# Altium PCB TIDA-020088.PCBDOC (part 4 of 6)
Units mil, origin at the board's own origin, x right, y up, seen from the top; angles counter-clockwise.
Board outline 7520.69 x 5119.11 mil, 6 copper layers (TOP, GND02, SIG03, SIG04, GND05, BOTTOM), stack 87.024 mil thick; 539 components, 269 nets, 1479 pads, 2085 vias.
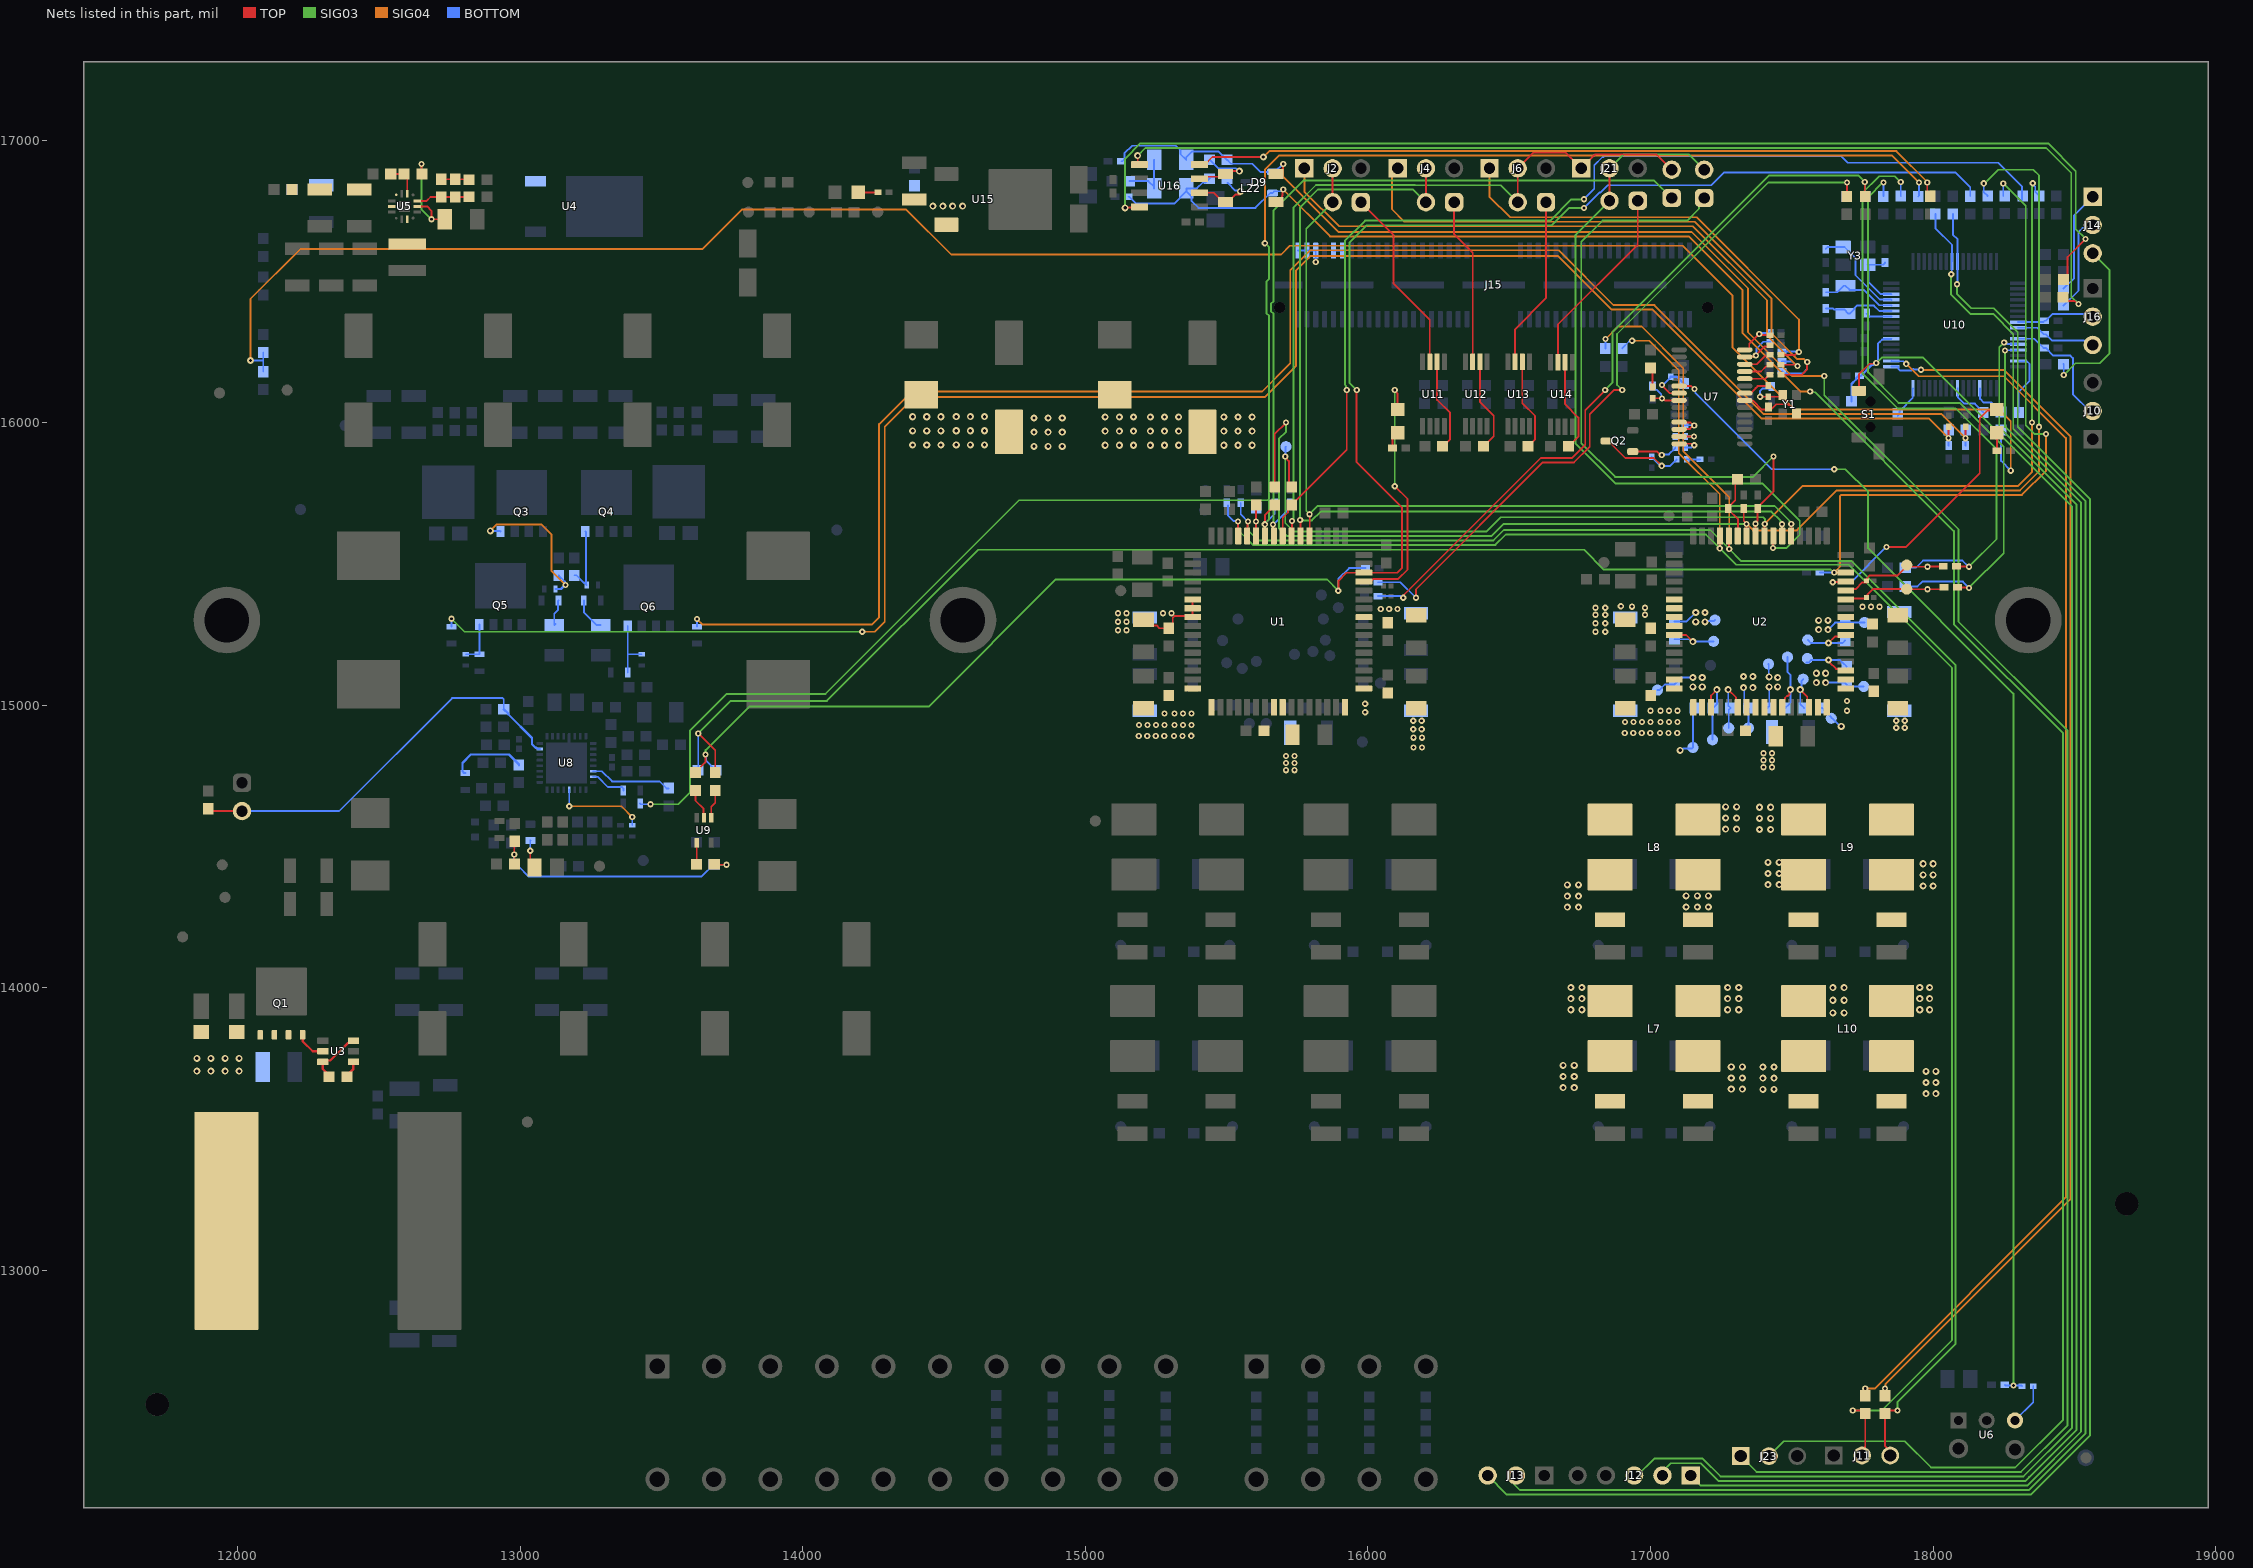
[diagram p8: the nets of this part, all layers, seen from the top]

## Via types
v1: diameter 25, hole 12, TOP to BOTTOM, tented both sides, 1621 vias
v2: diameter 22, hole 10, TOP to BOTTOM, tented both sides, 436 vias
v3: diameter 236.22, hole 137.8, TOP to BOTTOM, 15 vias
v4: diameter 19.68, hole 7.87, TOP to BOTTOM, tented both sides, 12 vias
v5: diameter 19.68, hole 7.87, TOP to BOTTOM, 1 vias

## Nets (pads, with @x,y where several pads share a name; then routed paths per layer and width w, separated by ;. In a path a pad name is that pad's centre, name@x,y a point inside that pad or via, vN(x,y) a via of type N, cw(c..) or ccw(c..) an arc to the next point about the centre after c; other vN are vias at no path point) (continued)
NETC71_2: C71.2 L7.4 TP36.1 U2.31 | length 144.5
  BOTTOM w6.5: TP36.1@17024.61,15053.26 17031.06,15053.26 17051.3,15073.5 C71.2@17085,15073.5 17085,15074.49 17098.7,15088.19 17099.69,15088.19 17109.5,15098 v1(17150,15098)
  other v1: 17272.91,13922.09 17312.28,13922.09 17272.91,13961.46 17312.28,13961.46 17272.91,14000.83 17312.28,14000.83 17150,15065 17183,15065 17183,15098
NETC72_1: C72.1 R20.1 TP33.1 U2.59 | length 367.9
  TOP w6.5: U2.59@17690.67,15374.37 17693.48,15377.19 17754.98,15377.19 C72.1@17761.06,15383.27 ; C72.1@17761.37,15383.58 C72.1@17764.02,15380.94 ; C72.1@17767.45,15383.58 17768.07,15384.2 17768.07,15391.89 17786.81,15410.63 TP33.1@17906.89,15410.63 17907.21,15410.32 17979.69,15410.32 v2(17980,15410) 18021.97,15410 18022.42,15410.45 18031.77,15410.45 R20.1@18038.58,15417.26
NETC73_1: C73.1 R22.2 TP35.1 U2.60 | length 392.8
  TOP w6.5: U2.60@17690.67,15405.87 17695.78,15410.98 17725.98,15410.98 17749.24,15434.24 17766.24,15434.24 17766.24,15449.12 17776.39,15459.27 17874.27,15459.27 TP35.1@17906.89,15491.89 ; TP35.1@17906.89,15495.63 17912.51,15490.01 17927.42,15490.01 ; 17927.43,15490 v2(17980,15490) 17980.66,15490.66 18035.57,15490.66 R22.2@18036.23,15491.32
NETC74_1: C74.1 L7.1 TP38.1 U2.25 | length 125.6
  BOTTOM w6.5: C74.1@17085,15296.5 17128.5,15296.5 v1(17160,15328) ; v1(17193,15295) 17195.87,15297.87 17224.94,15297.87 TP38.1@17228.07,15301
  other v1: 16717.91,13922.09 16757.28,13922.09 16717.91,13961.46 16757.28,13961.46 16717.91,14000.83 16757.28,14000.83 17160,15295 17193,15328
NETC74_2: C74.2 TP40.1 U2.26 | length 217.8
  TOP w6.5: U2.26@17084.37,15248.39 17126.61,15248.39 v1(17150,15225)
  BOTTOM w6.5: C74.2@17085,15233.5 17137.44,15233.5 17145.94,15225 v1(17150,15225) 17150.5,15225.5 17223,15225.5 TP40.1@17223.5,15226
NETC77_1: C77.1 L7.3 R21.1
  other v1: 17285.63,13641.26 17325,13641.26 17285.63,13680.63 17325,13680.63 17285.63,13720 17325,13720
NETC78_1: C78.1 L7.2 R23.1
  other v1: 16690.63,13646.26 16730,13646.26 16690.63,13685.63 16730,13685.63 16690.63,13725 16730,13725
NETC81_1: C81.1 TP41.1 U2.38 | length 218.4
  TOP w6.5: v1(17275,15055) 17302.95,15027.05 17302.95,14998.31 U2.38@17308.78,14992.48
  BOTTOM w6.5: v1(17275,15055) 17275,14998.5 C81.1@17283.5,14990 17276.87,14983.37 TP41.1@17276.87,14919.37
NETC81_2: C81.2 L8.4 TP42.1 U2.39 | length 150.1
  BOTTOM w6.5: v1(17329.18,15062.19) 17331.81,15059.56 17331.81,15003.7 17346.87,14988.64 TP42.1@17346.87,14919.37
  other v1: 17265.63,14561.26 17305,14561.26 17265.63,14600.63 17305,14600.63 17265.63,14640 17305,14640 17362.18,15062.19 17329.18,15101.56 17362.18,15101.56
NETC82_1: C82.1 L8.1 TP44.1 U2.34 | length 192.7
  BOTTOM w6.5: v1(17105,14840) 17109.06,14840 17115.31,14846.26 17146.26,14846.26 TP44.1@17150,14850 17150,14981.5 C82.1@17158.5,14990
NETC82_2: C82.2 TP46.1 U2.35 | length 255
  TOP w6.5: U2.35@17214.29,14992.48 17214.29,15034.29 v1(17235,15055)
  BOTTOM w6.5: TP46.1@17219.5,14877.5 17219.5,14988 C82.2@17221.5,14990 17235,15003.5 v1(17235,15055)
NETC85_1: C85.1 L8.3 R27.1
  other v1: 17126.26,14285.63 17165.63,14285.63 17205,14285.63 17126.26,14325 17165.63,14325 17205,14325
NETC86_1: C86.1 L8.2 R28.1
  other v1: 16705.63,14285 16745,14285 16705.63,14324.37 16745,14324.37 16705.63,14363.74 16745,14363.74
NETC89_1: C89.1 TP47.1 U2.46 | length 187.3
  TOP w6.5: v1(17530,15055) 17554.92,15030.08 17554.92,14998.31 U2.46@17560.75,14992.48
  BOTTOM w6.5: TP47.1@17540.4,15092.1 17534.78,15086.48 17534.78,15063.84 17530,15059.06 v1(17530,15055) 17530,15003.5 C89.1@17543.5,14990
NETC89_2: C89.2 L9.4 TP48.1 U2.47 | length 97.9
  BOTTOM w6.5: C89.2@17606.5,14990 17607.48,14990 17639.69,14957.79 TP48.1@17639.69,14953.51 17643.09,14953.51 17671.6,14925 v1(17675,14925)
NETC90_1: C90.1 L9.1 TP50.1 U2.42 | length 124.3
  BOTTOM w6.5: C90.1@17413.5,14990 17420,14996.5 v1(17420,15065) ; TP50.1@17417.33,15145.47 17418.67,15144.14 17418.67,15101.33 v1(17420,15100)
  other v1: 17385.63,14560 17425,14560 17385.63,14599.37 17425,14599.37 17385.63,14638.74 17425,14638.74 17450,15065 17450,15098
NETC90_2: C90.2 TP52.1 U2.43 | length 268.5
  TOP w6.5: U2.43@17466.26,14992.48 17466.26,15011.18 17475.93,15020.85 17475.93,15025.42 17483.51,15033.01 17486.39,15033.01 17492.24,15038.87 17492.24,15052.24 v1(17495,15055)
  BOTTOM w6.5: C90.2@17476.5,14990 17477.48,14990 17491.18,15003.7 17491.18,15004.69 17495,15008.5 v1(17495,15055) 17495,15106.99 17485,15116.99 TP52.1@17485,15170
NETC93_1: C93.1 L9.3 R30.1
  other v1: 17965,14360 18000,14360 17965,14399.37 18000,14399.37 17965,14438.74 18000,14438.74
NETC94_1: C94.1 L9.2 R31.1
  other v1: 17415.63,14365 17455,14365 17415.63,14404.37 17455,14404.37 17415.63,14443.74 17455,14443.74
NETC97_1: C97.1 TP53.1 U2.55 | length 213.1
  TOP w6.5: v1(17630,15220) 17652.56,15242.56 17684.84,15242.56 U2.55@17690.67,15248.39
  BOTTOM w6.5: TP53.1@17556.5,15231 17567.5,15220 v1(17630,15220) 17679.63,15220 C97.1@17688.79,15229.16
NETC97_2: C97.2 L10.4 TP54.1 U2.56 | length 139.4
  BOTTOM w6.5: v1(17628.28,15267.21) 17653.23,15292.16 C97.2@17688.79,15292.16 17689.46,15292.83 TP54.1@17757.1,15292.83
  other v1: 17952.91,13922.09 17987.91,13922.09 17952.91,13961.46 17987.91,13961.46 17952.91,14000.83 17987.91,14000.83 17595.28,15267.21 17595.28,15300.21 17628.28,15300.21
NETC98_1: C98.1 L10.1 TP56.1 U2.50 | length 140.4
  BOTTOM w6.5: v1(17620,15080) 17686.69,15080 C98.1@17693.83,15072.86 17700.3,15066.39 TP56.1@17754.72,15066.39
  other v1: 17645.63,13911.26 17685,13911.26 17645.63,13955.63 17685,13955.63 17645.63,14000 17685,14000 17587,15080 17587,15113 17620,15113
NETC98_2: C98.2 TP58.1 U2.51 | length 235.7
  TOP w6.5: v1(17630,15160) 17632.87,15157.13 17632.87,15152.21 17656.85,15128.23 17684.84,15128.23 U2.51@17690.67,15122.4
  BOTTOM w6.5: TP58.1@17551.77,15150.55 17559.72,15150.55 17569.17,15160 v1(17630,15160) 17669.69,15160 17679.14,15150.54 17680.13,15150.54 17693.83,15136.84 C98.2@17693.83,15135.86
NETC101_1: C101.1 L10.3 R32.1
  other v1: 17975,13625 18010,13625 17975,13664.37 18010,13664.37 17975,13703.74 18010,13703.74
NETC102_1: C102.1 L10.2 R33.1
  other v1: 17397.72,13640.45 17437.09,13640.45 17397.72,13679.82 17437.09,13679.82 17397.72,13719.19 17437.09,13719.19
NETC105_1: C105.1 C107.1 D1.2 D2.2 L12.2 Q1.1 Q1.2 Q1.3 U3.3 U3.6 | length 202.9
  TOP w8: C105.1@12327.44,13685 12327.44,13685.98 12300.87,13712.56 U3.6@12300.87,13737.6 12305.52,13742.25 12327.5,13742.25 12389.84,13804.59 12401.32,13804.59 U3.3@12409.13,13812.4
  other v1: 11855,13705 11905,13705 11955,13705 12005,13705 11855,13750 11905,13750 11955,13750 12005,13750
NETC105_2: C105.2 U3.1 | length 63.6
  TOP w8: C105.2@12382.56,13685 12382.56,13685.98 12409.13,13712.56 U3.1@12409.13,13737.6
NetC108_1: C108.1 L11.2 U4.3
NETC119_1: C119.1 R36.1 R37.1 U5.11 | length 189.6
  TOP w6.5: U5.11@12635.28,16784.69 12668.23,16784.69 12682.05,16798.5 R37.1@12720,16798.5 C119.1@12770,16798.5 12817.01,16798.5 R36.1@12818.5,16800
NETC119_2: C119.2 R37.2 R38.1 | length 99.1
  TOP w6.5: R37.2@12720,16861.5 C119.2@12770,16861.5 12817.01,16861.5 R38.1@12818.5,16860
NetC120_1: C120.1 C121.1 L13.2 U5.1 U5.3 | length 8.7
  TOP w6.5: U5.3@12536.02,16765 U5.3@12544.72,16765
NETC122_1: C122.1 R40.1 U5.10 | length 378.9
  TOP w6.5: U5.10@12635.28,16765 12670,16765 12685.28,16749.72 v2(12685.28,16720) C122.1@12732.91,16720 ; v2(12650,16915) 12650,16881.5 R40.1@12651.5,16880
  SIG03 w6.5: v2(12650,16915) 12650,16755.28 v2(12685.28,16720)
NETC128_1: C128.1 U7.7 Y1.3 | length 219.6
  TOP w6.5: U7.7@17333.42,16078.57 17334.9,16077.1 17362.9,16077.1 17393.73,16046.27 17426.27,16046.27 17445,16065 17486.22,16065 17517.13,16034.09 Y1.3@17517.13,16032.13
NETC129_1: C129.1 R45.1 Y1.1 | length 155.1
  TOP w6.5: v2(17388.03,16091.68) R45.1@17417.28,16091.68 17465.51,16091.68 Y1.1@17472.67,16098.85
  BOTTOM w6.5: v2(17388.03,16091.68) 17388.03,16112.32 17396.83,16121.13 17422.38,16121.13 C129.1@17428.61,16127.36
NetC130_1: C130.1 J2.1 R43.2 | length 2277.3
  TOP w6.5: R43.2@17461.97,16204.56 17462.19,16204.78 17511.97,16204.78 17516.75,16200 v2(17520,16200)
  SIG04 w6.5: J2.1@15775,16900 15775,16817.63 15897.63,16695 17149.75,16695 17412.5,16432.24 17412.5,16307.5 v2(17520,16200)
  BOTTOM w6.5: C130.1@17465.9,16216.37 17500.38,16216.37 17516.75,16200 v2(17520,16200)
NetC131_1: C131.1 J4.1 R44.2 | length 2168.7
  TOP w6.5: R44.2@17461.97,16169.56 17534.56,16169.56 17554,16189 17554,16214 v2(17555,16215)
  SIG04 w6.5: J4.1@16105,16900 16085,16880 16085,16755 16129,16711 17156.37,16711 17428.5,16438.87 17428.5,16315.39 17518.89,16225 17543.14,16225 17553.14,16215 v2(17555,16215)
  BOTTOM w6.5: C131.1@17465.9,16181.37 17472.27,16175 17540,16175 17555,16190 v2(17555,16215)
NetC132_1: C132.1 J6.1 R46.2 | length 1617.2
  TOP w6.5: R46.2@17461.97,16239.56 17462.19,16239.78 17511.53,16239.78 17521.75,16250 v2(17525,16250)
  SIG04 w6.5: J6.1@16430,16900 16430,16800 16503,16727 17163,16727 17525,16365 v2(17525,16250)
  BOTTOM w6.5: C132.1@17465.9,16251.37 17523.63,16251.37 v2(17525,16250)
NETC136_1: C136.1 R52.2 U7.22 | length 153.9
  TOP w6.5: R52.2@17007.28,16086.68 17007.93,16086.04 17039.59,16086.04 v2(17040.24,16085.39) 17043.49,16085.39 17050.3,16078.57 U7.22@17101.14,16078.57
  BOTTOM w6.5: C136.1@17007.28,16123.24 17007.28,16122.4 17013.55,16116.13 17022.33,16116.13 17037.94,16100.51 17037.94,16087.69 v2(17040.24,16085.39)
NetC137_1: C137.1 R52.1 | length 70.5
  TOP w8: C137.1@17000,16193.5 17006.7,16186.81 17006.7,16126.64 R52.1@17007.28,16126.06
NETC138_1: C138.1 R53.1 U7.21 | length 170.3
  TOP w6.5: v2@17041.61,16131.21 17068.65,16104.17 U7.21@17101.14,16104.17
  BOTTOM w6.5: v2(17041.07,16132.74) 17043.86,16132.74 17071.74,16160.61 R53.1@17071.74,16162.58
  BOTTOM w8: R53.1@17071.74,16162.58 17093.86,16162.58 17116.69,16139.75 C138.1@17116.69,16138.77
NetC139_1: C139.1 L21.2 U15.3
  other v1: 14460.19,16766.27 14495.19,16766.27 14530.19,16766.27 14565.19,16766.27
NetC140_2: C140.2 U10.24 | length 144.9
  BOTTOM w6.5: U10.24@18086.62,16121.37 18087.53,16120.47 18087.53,16089.53 18109.88,16067.18 18147.84,16067.18 18177.66,16037.37 C140.2@18177.66,16036.38
NetC173_1: C173.1 D9.1 J23.1 L22.4 R68.2 R69.2 | length 8408.7
  TOP w6.5: L22.4@15674.57,16879.21 15683.43,16879.21 15696.14,16891.93 15696.14,16895.49 15698.44,16897.79 15698.44,16913.44 v2(15700,16915)
  SIG03 w6.5: J23.1@17319.17,12342.19 17375.36,12286 18311,12286 18476,12451 18476,14909 18090,15295 18090,15622.63 17615,16097.63 v2(17615,16165)
  SIG04 w6.5: v2(15700,16915) 15700,16870 15895,16675 17145,16675 17345,16475 17345,16320 17500,16165 v2(17615,16165)
  BOTTOM w6.5: C173.1@15127.24,16925 15131.18,16925 15137.99,16931.81 15137.99,16952.99 15165,16980 15320,16980 15336.5,16963.5 15336.5,16950.59 R69.2@15357.09,16930 15357.09,16939.11 15377.68,16959.7 15470.81,16959.7 15500.51,16930 R68.2@15501.5,16930 15515.2,16916.3 15590.04,16916.3 15618.94,16887.4 D9.1@15662.24,16887.4 15670.61,16887.4 15698.21,16915 v2(15700,16915)
NETC175_2: C175.2 R86.2 | length 100.1
  BOTTOM w6.5: R86.2@13125,15288.15 R86.2@13120,15283.15 13120,15323.65 13133.85,15337.5 13133.85,15368.85 C175.2@13135,15370
NETC176_2: C176.2 R91.2 | length 118.8
  BOTTOM w6.5: C176.2@13225,15370 13225,15329.35 13271.2,15283.15 R91.2@13284,15283.15
NETC184_1: C184.1 J9.2 R83.2 U8.7 | length 1453.2
  TOP w6.5: R83.2@11895,14633.5 11903.5,14625 J9.2@12015,14625
  BOTTOM w6.5: J9.2@12015,14625 12358.33,14625 12758.33,15025 12937.69,15025 12941.5,15021.19 C184.1@12941.5,14985
  BOTTOM w8: C184.1@12941.5,14985 12942.48,14985 12957.18,14970.3 12957.18,14968.28 13041.27,14884.19 13041.27,14861.5 13053.66,14849.11 13057.52,14849.11 13061.78,14844.84 U8.7@13068.67,14844.84
NETC188_2: C188.2 R100.1 R105.2 R106.1 R112.2 | length 952.7
  TOP w6.5: R112.2@12979,14437.77 12978.31,14438.46 v2(12978.31,14471.69) 12978.31,14516.18 R105.2@12980.63,14518.5 ; R106.1@13686.48,14437.13 13688.61,14435 v2(13730,14435)
  BOTTOM w6.5: v2(12978.31,14471.69) 12977.18,14470.57 12977.18,14438.9 C188.2@12976.05,14437.77 12976.05,14436.79 12983.85,14428.99 12993.69,14428.99 13028.74,14393.94 13642.31,14393.94 13685.49,14437.13 R100.1@13686.48,14437.13 13688.61,14435 v2(13730,14435)
NETC190_1: C190.1 R116.1 | length 102.9
  TOP w6.5: v2(13035,14485) 13035,14440 C190.1@13050,14425
  BOTTOM w6.5: v2(13035,14485) 13035,14520.83 R116.1@13035.63,14521.46
NetC191_2: C191.2 R119.2 | length 271
  BOTTOM w8: R119.2@12805,14760 12801,14760 12795,14766 12795,14795.41 12824.79,14825.2 12959.6,14825.2 12995.11,14789.69 C191.2@12995.11,14788.7 C191.2@12995.11,14787.72
NETC201_1: C201.1 U10.32 | length 120.2
  BOTTOM w6.5: C201.1@17875,16023.62 17881.81,16030.43 17881.81,16040.87 17928.24,16087.3 17928.24,16120.47 U10.32@17929.14,16121.37
NetC204_1: C204.1 D9.2 J23.2 L22.3 R72.1 R80.2 | length 8252.4
  TOP w6.5: L22.3@15674.57,16780.79 15683.43,16780.79 15696.14,16793.5 15696.14,16802.36 15697.7,16803.92 15697.7,16822.7 v2(15700,16825)
  SIG03 w6.5: J23.2@17419.17,12342.19 17471.98,12395 17900,12395 17993,12302 18290.96,12302 18460,12471.04 18460,14900 18074,15286 18074,15616 17582.3,16107.7 17567.3,16107.7 v2(17565,16110)
  SIG04 w6.5: v2(15700,16825) 15866,16659 17136,16659 17325,16470 17325,16317.37 17532.37,16110 v2(17565,16110)
  BOTTOM w6.5: C204.1@15151.62,16799.33 15155.55,16799.33 15179.88,16775 15314.3,16775 R72.1@15357.44,16818.15 ; R80.2@15445.12,16870 15423.85,16848.73 15414.35,16848.73 15394.59,16828.97 R72.1@15357.44,16828.97 R72.1@15357.44,16818.15 ; v2(15700,16825) 15696.75,16825 15690.6,16818.85 15668.5,16818.85 D9.2@15662.24,16812.6 15654.37,16812.6 15601.77,16760 15481.4,16760 15481.15,16759.75 15400.25,16759.75 15375.84,16784.15 15375.84,16799.75 R72.1@15357.44,16818.15
NETD3_2: D3.2 R39.2 | length 69.3
  TOP w6.5: D3.2@14196.34,16815 R39.2@14265.63,16815
NETD4_1: D4.1 Q2.3 R57.2 | length 346.7
  TOP w6.5: Q2.3@16842.76,15935 16850.63,15935 16910.84,15874.79 17011.89,15874.79 v2(17039.68,15847)
  BOTTOM w6.5: R57.2@17004.37,15879.69 17004.37,15877.72 17032.79,15849.3 17037.38,15849.3 v2(17039.68,15847) 17069.28,15847 17085.47,15863.19 17087.44,15863.19 17092.28,15868.03 D4.1@17092.28,15870
NETD4_2: D4.2 R54.1 | length 47.6
  BOTTOM w6.5: D4.2@17127.72,15870 R54.1@17175.31,15870
NETD7_1: D7.1 R171.2 | length 61.4
  TOP w6.5: R171.2@16086.38,15910 16086.38,15945.04 D7.1@16105,15963.66
NETD7_2: D7.2 U1.61 | length 898.4
  TOP w6.5: U1.61@15985.67,15437.36 15991.5,15443.19 16014.24,15443.19 16018.09,15447.03 16107.03,15447.03 16140,15480 16140,15730 v2(16095,15775) ; v2(16095,16115) 16095,16111.75 16105,16101.75 D7.2@16105,16046.34
  SIG03 w6.5: v2(16095,15775) v2(16095,16115)
NETD8_1: D8.1 R173.2 | length 64.2
  TOP w6.5: D8.1@18225,15963.66 18226.38,15962.28 R173.2@18226.38,15900
NETD8_2: D8.2 U2.61 | length 994.1
  TOP w6.5: v2(17645,15435) 17646.18,15436.18 17689.49,15436.18 U2.61@17690.67,15437.36 ; v2(17835,15560) 17905,15560 18165.25,15820.25 18165.25,16015.25 18192.24,16042.24 18220.9,16042.24 D8.2@18225,16046.34
  BOTTOM w6.5: v2(17645,15435) 17710,15435 v2(17835,15560)
NETJ2_2: J2.2 J3.2 U1.5 U2.5 | length 3129.2
  TOP w6.5: v2(15792.66,15675.78) 15793.88,15674.56 15793.88,15599.9 U1.5@15792.76,15598.78 ; J3.2@15875,16780 J2.2@15875,16900 ; U2.5@17497.76,15598.78 17497.94,15598.96 17497.94,15640.73 v2(17498.12,15640.92)
  SIG03 w6.5: v2(15792.66,15675.78) 15792.66,15677.11 15781.61,15688.16 15781.61,16686.61 J3.2@15875,16780 ; v2@15796.5,15679.78 15821.72,15705 17438.89,15705 17492.16,15651.73 17492.16,15650.12 17498.12,15644.16 v2(17498.12,15640.92)
NetJ3_1: J3.1 U11.3 | length 667.6
  TOP w6.5: J3.1@15975,16780 16090,16665 16090,16493.63 16218.82,16364.81 U11.3@16218.82,16218.86 ; U11.3@16214.96,16218.86 U11.3@16218.82,16215
NETJ4_2: J4.2 J17.2 U1.6 U2.6 | length 3557.1
  TOP w6.5: v2(15760,15655) 15760.63,15654.37 15760.63,15599.41 U1.6@15761.26,15598.78 ; J17.2@16205,16780 J4.2@16205,16900 ; v2(17465.56,15640.46) 17465.91,15640.11 17465.91,15599.13 U2.6@17466.26,15598.78
  SIG03 w6.5: J17.2@16205,16780 16160.48,16824.52 15843.74,16824.52 15843.25,16825 15822.63,16825 15760,16762.37 v2(15760,15655) 15761.22,15653.78 15801.78,15653.78 15833,15685 17427.78,15685 17460.56,15652.22 17460.56,15648.71 17465.56,15643.7 v2(17465.56,15640.46)
NETJ6_2: J6.2 J18.2 J21.1 J22.2 U1.7 | length 2771.3
  TOP w6.5: U1.7@15729.76,15598.78 15730.59,15599.6 15730.59,15650.59 v2(15731.41,15651.41) ; J18.2@16530,16780 J6.2@16530,16900 16585,16955 16700,16955 J21.1@16755,16900 16805,16950 17020,16950 J22.2@17075,16895
  SIG03 w6.5: v2(15731.41,15651.41) 15731.41,15654.66 15737,15660.25 15737,16762 15816,16841 15849.88,16841 15850.36,16840.52 16167.11,16840.52 16167.63,16840 16470,16840 J18.2@16530,16780
NETJ11_2: J11.2 R15.1 R123.2 R157.2 U1.13 U2.13 | length 6953.9
  TOP w6.5: v2(15540,15650) 15540.39,15649.61 15540.39,15599.17 U1.13@15540.79,15598.78 ; v2(17245,15555) 17245.39,15555.39 17245.39,15598.39 U2.13@17245.79,15598.78 ; v2(17715.48,12503.7) 17760,12503.7 17760,12376.72 17758.78,12375.5 17758.78,12354.51 J11.2@17748.64,12344.37
  SIG03 w6.5: v2(15540,15650) 15540,15620 15593,15567 16450.85,15567 16487.85,15604 17196,15604 v2(17245,15555) 17303,15497 17701.84,15497 18067,15131.84 18067,12752 17818.7,12503.7 v2(17715.48,12503.7)
  SIG04 w6.5: v2(16935,16290) 16995.67,16290 17100.06,16185.61 17100.06,15892.31 17245,15747.37 v2(17245,15555)
  BOTTOM w6.5: R15.1@15505,15706.38 15505,15670.23 15522.93,15652.3 15537.7,15652.3 v2(15540,15650) ; R157.2@16900,16262.13 16900,16263.11 16923.92,16287.03 16932.03,16287.03 v2(16935,16290)
NETJ11_3: J11.3 R16.1 R128.2 R158.2 U1.12 U2.12 | length 6973.7
  TOP w6.5: U1.12@15572.28,15598.78 15573.64,15600.14 15573.64,15648.64 v2(15575,15650) ; U2.12@17277.28,15598.78 17277.89,15598.18 17277.89,15553.23 v2(17278.49,15552.62) ; J11.3@17848.64,12344.37 17848.64,12358.71 17830,12377.35 17830,12503.7 v2(17874.52,12503.7)
  SIG03 w6.5: v2(15575,15650) 15575,15620 15612,15583 16444.22,15583 16481.22,15620 17211.11,15620 v2(17278.49,15552.62) 17321.11,15510 17711.47,15510 18080,15141.47 18080,12740 17874.52,12534.52 v2(17874.52,12503.7)
  SIG04 w6.5: v2(16840.61,16295.8) 16885.27,16340.46 16968.15,16340.46 17116.06,16192.56 17116.06,15898.94 17278.49,15736.51 v2(17278.49,15552.62)
  BOTTOM w6.5: R16.1@15550,15716.38 15550,15675 v2(15575,15650) v2@15575,15653.25 ; R158.2@16840,16262.13 16840.61,16262.73 v2(16840.61,16295.8)
NETJ14_1: J14.1 R147.2 | length 367.8
  BOTTOM w6.5: R147.2@18461.5,16475 18462.48,16475 18499,16511.52 18499,16733.37 J14.1@18565,16799.37
NETJ14_2: J14.2 R150.2 | length 342.8
  BOTTOM w6.5: R150.2@18461.5,16415 18462.48,16415 18515,16467.52 18515,16675 18528.85,16688.85 18554.48,16688.85 J14.2@18565,16699.37
NETJ14_3: J14.3 R151.2 | length 612.7
  SIG03 w6.5: v2(18462.51,16168.32) 18504.2,16210 18590,16210 18625,16245 18625,16539.37 J14.3@18565,16599.37
  BOTTOM w6.5: R151.2@18461.89,16207.27 18462.51,16206.64 v2(18462.51,16168.32)
NETJ15_2: J15.2 J15.4 J15.6 | length 104
  BOTTOM w6.5: J15.2@15752.28,16608.92 J15.4@15783.77,16608.92 J15.6@15815.27,16608.92 15815.13,16608.78 15815.13,16568.13 v2(15815,16568)
NETJ15_10: J15.10 J15.12 | length 31.5
  BOTTOM w6.5: J15.10@15878.26,16608.92 J15.12@15909.76,16608.92
NetJ17_1: J17.1 U12.3 | length 597.6
  TOP w6.5: J17.1@16305,16780 16305,16667.44 16370.59,16601.85 U12.3@16370.59,16215 U12.3@16366.73,16218.86
NetJ18_1: J18.1 U13.3 | length 613.5
  TOP w6.5: U13.3@16520.59,16215 16516.73,16218.86 16520.59,16222.72 16520.59,16330.59 16630,16440 J18.1@16630,16780
NetJ19_1: J19.1 U14.3 | length 688
  TOP w6.5: U14.3@16672.2,16214.17 16672.2,16347.2 16955,16630 J19.1@16955,16785
NetJ19_2: J19.2 J20.2 J21.2 U2.7 | length 2515.1
  TOP w6.5: J19.2@16855,16785 J21.2@16855,16900 ; v2(17433.31,15556.49) 17434.04,15557.22 17434.04,15598.05 U2.7@17434.76,15598.78
  SIG03 w6.5: J19.2@16855,16785 16735,16665 16735,15925 16875,15785 17395,15785 17528.01,15651.99 17528.01,15603.01 17481.49,15556.49 v2(17433.31,15556.49) ; J21.2@16855,16900 16905,16950 17135,16950 J20.2@17190,16895
NetJ20_1: J20.1 R26.1 U2.9 | length 2290.3
  TOP w6.5: U2.9@17371.77,15598.78 17371.65,15598.9 17371.65,15641.75 v2(17371.53,15641.87) 17371.53,15645.12 17378.86,15652.45 17378.86,15695.24 R26.1@17380,15696.38 17380,15700.32 17435,15755.32 v2(17435,15880)
  SIG03 w6.5: J20.1@17190,16795 17171.67,16776.67 17171.67,16756.67 17130,16715 16830,16715 16755,16640 16755,15927.63 16874.63,15808 17363,15808 v2(17435,15880)
NetJ22_1: J22.1 R7.1 U1.9 | length 2744.4
  TOP w6.5: v2(15663.57,15639.62) 15665.17,15638.02 15665.17,15600.38 U1.9@15666.77,15598.78
  SIG03 w6.5: v2(15663.57,15639.62) 15665.3,15641.35 15665.3,15650.92 15666,15651.62 15666,16385.1 15656.63,16394.47 15656.63,16420.22 15666,16429.58 15666,16751 15771.52,16856.52 15812.04,16856.52 15812.52,16857 15856.51,16857 15856.99,16856.52 17013.48,16856.52 J22.1@17075,16795
  BOTTOM w6.5: v2(15663.57,15639.62) 15665.76,15639.62 15719.37,15693.23 15719.37,15710.75 R7.1@15725,15716.38
NETL15_1: L15.1 U5.7
NetL22_1: L22.1 R68.1 U16.7 | length 274.9
  TOP w6.5: U16.7@15404.18,16863.35 15410.83,16870 15486.22,16870 15506.22,16890 v1(15545,16890)
  BOTTOM w6.5: R68.1@15438.5,16930 15439.49,16930 15469.49,16900 15531.94,16900 15541.94,16890 v1(15545,16890)
NetL22_2: L22.2 R80.1 U16.6 | length 229.9
  TOP w6.5: U16.6@15404.18,16813.35 15454.01,16813.35 15486.57,16780.79 L22.2@15495.43,16780.79 15504.29,16780.79 15530.63,16807.13 15547.13,16807.13 v1@15550,16810
  BOTTOM w6.5: R80.1@15502.45,16848.41 15503.44,16848.41 15530.57,16821.28 15545.61,16821.28 v1(15548.48,16818.41)
NETQ1_4: Q1.4 U3.5 | length 115.4
  TOP w8: Q1.4@12230,13840 12230,13810 12265,13775 U3.5@12300.87,13775
NETQ2_1: Q2.1 R50.1 | length 167.5
  TOP w6.5: Q2.1@16937.24,15897.6 17023.83,15897.6 17036.43,15885 v2(17039.68,15885)
  BOTTOM w6.5: v2(17039.68,15885) 17041.98,15887.3 17064.86,15887.3 17087.28,15909.72 R50.1@17087.28,15911.68
NETQ3_4: Q3.4 R73.1 R75.2 | length 561.9
  SIG04 w6.5: v1(12893.95,15616.88) 12917.07,15640 13074.14,15640 13110,15604.14 13110,15475 v2(13160,15425)
  BOTTOM w6.5: v1(12893.95,15616.88) 12928.12,15616.88 Q3.4@12930,15615
  BOTTOM w8: R75.2@13124.42,15411.01 13143.92,15411.01 13157.91,15425 v2(13160,15425) 13157.32,15427.68 13157.32,15436.45 13136.25,15457.52 R73.1@13136.25,15458.5
NETQ4_4: Q4.4 R74.2 R76.2 | length 244.9
  BOTTOM w6.5: R74.2@13191.25,15460 13198.75,15460 13226.75,15432 R76.2@13232.5,15432 ; Q4.4@13230,15615 13232.5,15612.5 R76.2@13232.5,15432 ; R76.2@13235,15425 13232.5,15427.5 R76.2@13232.5,15432
NETQ5_4: Q5.4 R84.2 R92.2 | length 153.2
  BOTTOM w6.5: R92.2@12806.83,15180 R84.2@12855,15180 Q5.4@12855,15285
NETQ6_4: Q6.4 R85.1 R93.2 | length 215
  BOTTOM w6.5: R85.1@13380,15115 13380,15180 ; Q6.4@13380,15279.96 13380,15180 ; R93.2@13430,15180 13380,15180
NETR1_2: R1.2 R61.1 R125.2 | length 2640.4
  TOP w6.5: v2(16125,15380) 16127.3,15382.3 16127.3,15389.92 16612.37,15875 16722.54,15875 16769,15921.46 16769,16044 16839.44,16114.44 v2(16839.44,16115.56) ; v2(17758.13,16851.87) 17758.13,16802.26 R61.1@17760,16800.39
  SIG03 w6.5: v2(16839.44,16115.56) 16865,16141.11 16865,16320 17420,16875 17735,16875 v2(17758.13,16851.87)
  BOTTOM w6.5: R1.2@16035.21,15385.87 16115.89,15385.87 16121.75,15380 v2(16125,15380) ; v2(17758.13,16851.87) 17758.13,16802.26 R125.2@17760,16800.39
NETR3_1: R3.1 R60.1 R130.2 | length 2618.8
  TOP w6.5: v2(16170,15380) 16170,15410 16619,15859 16729.16,15859 16785,15914.84 16785,16030 16870,16115 v2(16900,16115) ; R60.1@17695,16800.39 v2(17695,16850)
  SIG03 w6.5: v2(16900,16115) 16881.3,16133.7 16881.3,16313.67 17417.63,16850 v2(17695,16850)
  BOTTOM w6.5: R3.1@16035,15435 16115,15435 v2(16170,15380) ; R130.2@17695,16800.39 v2(17695,16850)
NETR5_1: R5.1 R102.1 R113.1 R138.2 U1.62 | length 6686
  TOP w6.5: R102.1@13620,14761.5 13620,14762.48 13655,14797.48 v2(13655,14825) ; v2(15895,15405) 15896,15406 15896,15441 15923.86,15468.86 U1.62@15985.67,15468.86 16103.86,15468.86 16120.86,15485.86 16120.86,15699.14 15960,15860 v2(15960,16115)
  SIG03 w6.5: v2(13655,14825) 13655.88,14825.88 13655.88,14840.88 13810,14995 14445,14995 14895,15445 15855,15445 v2(15895,15405) ; v2(15960,16115) 15934.21,16140.79 15934.21,16636.58 15995.92,16698.29 16650.92,16698.29 16712.63,16760 v2(16765,16760)
  BOTTOM w6.5: v2(13655,14825) 13657.3,14822.7 13657.3,14803.22 13690.51,14770 R113.1@13691.5,14770 ; v2(15895,15405) 15895,15446.75 15933.25,15485 R5.1@15991.38,15485 ; v2(16765,16760) 16820,16815 16823.51,16815 16848.51,16840 17215,16840 17259.74,16884.74 18080.26,16884.74 18131.61,16833.39 R138.2@18131.61,16801.63
NETR6_1: R6.1 R9.1 R98.1 R137.2 U1.10 | length 6715.6
  TOP w6.5: U1.10@15635.28,15598.78 15635.17,15598.88 15635.17,15639.83 15635,15640 15635,15672.52 15670,15707.52 R9.1@15670,15708.5
  SIG03 w6.5: v2(13460.37,14649.37) 13559.37,14649.37 13600.02,14690.02 13600.02,14910.02 13730,15040 14080,15040 14765,15725 15645,15725 15650,15730 ; v2(15635,16635) 15650,16620 15650,16508.61 15640.63,16499.24 15640.63,16387.84 15650,16378.47 15650,15730 ; v2(15635.07,15639.93) 15635.07,15643.32 15650,15658.25 15650,15725 15650,15730
  SIG04 w6.5: v2(15635,16635) 15635,16895 15685,16945 17855,16945 v2@17947,16853
  BOTTOM w6.5: R98.1@13423.97,14651.78 13426.38,14649.37 v2(13460.37,14649.37) ; v2(15635.07,15639.93) 15635.07,15642.8 15670,15677.74 R6.1@15670,15716.38 ; R137.2@17947.38,16800.33 17950,16802.96 v2(17950,16850)
NetR9_2: R9.2 R25.1 R140.2 U2.10 | length 4864.5
  TOP w6.5: R9.2@15670,15771.5 15670,15960 v2(15710,16000) ; R25.1@17330,15696.38 17330,15653.3 17340.04,15643.26 v2(17340.04,15641.44) 17340.16,15641.33 17340.16,15598.9 U2.10@17340.28,15598.78
  SIG03 w6.5: v2(15710,16000) 15710,15968.14 15685,15943.14 15685,15626.72 15712.72,15599 16437.59,15599 16480.03,15641.44 v2(17340.04,15641.44) ; v2@18182.21,16847.21 18230,16895 18355,16895 18375,16875 v2(18375,15985)
  SIG04 w6.5: v2(17340.04,15641.44) 17363.03,15618.46 17517.92,15618.46 17659.47,15760 18307.63,15760 18375,15827.37 v2(18375,15985)
  BOTTOM w6.5: v2(18179.14,16846.79) 18179.14,16822.72 18179.18,16822.68 18179.18,16815.88 R140.2@18192.88,16802.18
NETR11_1: R11.1 R22.1 R133.2 | length 2187.9
  TOP w6.5: R22.1@18083.47,15491.32 18084.13,15490.66 18126.34,15490.66 v2(18127,15490)
  SIG03 w6.5: v2(17885.84,16851.22) 17865.06,16872 17809.37,16872 17750,16812.63 17750,16175 17875,16050 18080,16050 18225,15905 18225,15588 v2(18127,15490)
  BOTTOM w6.5: R133.2@17885.55,16801.74 17885.84,16802.04 v2(17885.84,16851.22) ; R11.1@17901.51,15486.7 17939.57,15486.7 17964.87,15512 18103.8,15512 18125.8,15490 v2(18127,15490)
NETR18_2: R18.2 R19.1 U1.11 | length 167.7
  TOP w6.5: U1.11@15603.78,15598.78 15603.89,15598.89 15603.89,15649.89 v2(15604,15650) 15604,15707.5 R19.1@15605,15708.5
  BOTTOM w6.5: v2(15604,15650) R18.2@15604,15707.5
NETR20_2: R20.2 R29.1 R132.2 | length 2171.8
  TOP w6.5: R20.2@18085.82,15417.26 18086.95,15416.13 18125.87,15416.13 v2(18127,15415)
  SIG03 w6.5: v2(17825,16850) 17821.75,16850 17770,16798.25 17770,16177.63 17877.63,16070 18095,16070 18250,15915 18250,15538 v2(18127,15415)
  BOTTOM w6.5: R132.2@17823.6,16801.88 R132.2@17823.6,16800.89 17825,16802.29 v2(17825,16850) ; R29.1@17901.5,15420 17944.42,15420 17961.68,15437.26 18105.42,15437.26 18127,15415.68 v2(18127,15415)
NETR24_1: R24.1 R109.2 R113.2 R141.2 U2.62 | length 6892.3
  TOP w6.5: v2(13630,14900) 13690,14840 R109.2@13690,14761.5 ; v2(17650,15470) 17650.57,15469.43 17690.1,15469.43 U2.62@17690.67,15468.86
  SIG03 w6.5: v2(13630,14900) 13745,15015 14085,15015 14620,15550 16765,15550 16835,15480 17638.14,15480 17648.14,15470 v2(17650,15470) ; v2@18251.66,16843.34 18328,16767 18328,15990.89 18358.89,15960 v2(18400,15960)
  SIG04 w6.5: v2(17650,15470) 17670.75,15490.75 17670.75,15740.19 17674.56,15744 18314.25,15744 18400,15829.75 v2@18400,15955
  BOTTOM w6.5: R113.2@13628.5,14770 13630,14771.5 v2(13630,14900) ; R24.1@17599.1,15470 v2(17650,15470) ; R141.2@18248.15,16801.44 v2(18248.15,16846.05)
NETR34_1: R34.1 R35.2 U2.11 | length 230.1
  TOP w6.5: R35.2@17308.5,15800 17300,15791.5 17300,15725.32 17275,15700.32 R34.1@17275,15696.38 17275,15692.44 17310,15657.44 17310,15600 U2.11@17308.78,15598.78
NETR40_2: R40.2 R41.2 U5.13 | length 121.4
  TOP w6.5: R41.2@12541.5,16880 R40.2@12588.5,16880 12599.84,16868.66 U5.13@12599.84,16810.28
NETR42_1: R42.1 U6.3 | length 147.8
  BOTTOM w6.5: U6.3@18290,12468.86 18354.37,12533.23 R42.1@18354.37,12590
NETR43_1: R43.1 U7.11 | length 99
  TOP w6.5: U7.11@17333.42,16180.94 17390.94,16180.94 17409.72,16199.72 17417.75,16199.72 R43.1@17422.6,16204.56
NETR44_1: R44.1 U7.10 | length 95.1
  TOP w6.5: U7.10@17333.42,16155.35 17406.41,16155.35 17420.63,16169.56 R44.1@17422.6,16169.56
NETR45_2: R45.2 U7.8 | length 95.2
  TOP w6.5: U7.8@17333.42,16104.17 17354.21,16104.17 17359.94,16109.9 17360.35,16109.9 17371.98,16121.53 17371.98,16121.94 17379.13,16129.09 17415.31,16129.09 R45.2@17417.28,16131.06
NETR46_1: R46.1 U7.12 | length 102.9
  TOP w6.5: U7.12@17333.42,16206.53 17376.5,16206.53 17404.69,16234.72 17417.75,16234.72 R46.1@17422.6,16239.56
NETR47_1: R47.1 U7.25 U7.26 | length 148.7
  TOP w6.5: U7.26@17101.14,15976.21 17102.61,15977.69 17139.44,15977.69 v2@17151.75,15990 ; U7.25@17101.14,16001.8 17102.61,16000.33 17141.43,16000.33 v2@17151.75,15990 ; v2(17155,15990) v2@17151.75,15990
  BOTTOM w6.5: R47.1@17121.97,15991.37 17122.65,15990.68 17154.31,15990.68 v2(17155,15990)
NETR48_1: R48.1 U7.28 | length 92.1
  TOP w6.5: U7.28@17101.14,15925.03 17146.72,15925.03 17151.75,15920 v2(17155,15920)
  BOTTOM w6.5: R48.1@17122.28,15911.68 17143.6,15911.68 17151.91,15920 v2(17155,15920)
NETR48_2: R48.2 R50.2 U7.27 | length 120.5
  TOP w6.5: U7.27@17101.14,15950.62 v2(17154.38,15950.62)
  BOTTOM w6.5: R50.2@17087.28,15951.06 R48.2@17122.28,15951.06 17122.5,15950.84 17154.16,15950.84 v2(17154.38,15950.62)
NETR55_1: R55.1 R56.2 U7.13 | length 189.5
  TOP w6.5: U7.13@17333.42,16232.12 17334.9,16233.59 17365.35,16233.59 17371.75,16240 17375,16240 17404.72,16269.72 17417.75,16269.72 R56.2@17422.59,16274.56
  BOTTOM w6.5: v2(17372.82,16237.82) 17375.12,16240.12 17375.12,16262.08 17399.41,16286.37 R55.1@17422.6,16286.37
NETR58_1: R58.1 R59.2 U7.14 | length 164.5
  TOP w6.5: U7.14@17333.42,16257.71 17346.08,16257.71 17349.64,16261.27 17349.64,16278.64 v2(17385,16314) ; v2@17383.81,16309.56 R59.2@17422.59,16309.56
  BOTTOM w6.5: v2(17385,16314) 17387.3,16316.3 17394.54,16316.3 17395.78,16317.54 17418.76,16317.54 R58.1@17422.6,16321.37
NetR66_2: R66.2 U10.15 | length 232
  BOTTOM w6.5: U10.15@18301.19,16217.83 18302.09,16216.92 18332.26,16216.92 18341.72,16207.46 18341.72,16148.52 18303.11,16109.92 R66.2@18303.11,16036.29
NetR67_2: R67.2 U10.20 | length 132.2
  BOTTOM w6.5: U10.20@18165.36,16121.37 18166.27,16120.47 18166.27,16083.73 18179,16071 18207.55,16071 18240.55,16038 R67.2@18240.55,16037.02
NetR70_1: R70.1 U16.1 | length 3925.1
  TOP w6.5: v1(15185,16945) 15185,16919.93 U16.1@15191.58,16913.35 ; R70.1@18460.3,16444.05 18474,16430.35 18501.4,16430.35 18511.75,16420 v2(18515,16420)
  SIG03 w6.5: v1(15185,16945) 15212,16972 18400.37,16972 18489,16883.37 18489,16446 v2(18515,16420)
NetR71_1: R71.1 U16.8 | length 2695.1
  TOP w6.5: U16.8@15404.18,16913.35 15422.88,16913.35 15449.53,16940 v1(15630,16940) ; v2(17979.44,16849.44) 17979.44,16811.26 R71.1@17989.63,16801.07
  SIG04 w6.5: v1(15630,16940) 15651,16961 17870.11,16961 17979.44,16851.67 v2(17979.44,16849.44)
NetR79_1: R79.1 U16.4 | length 4084.6
  TOP w6.5: v1(15140.56,16760.13) 15142.17,16761.74 15189.97,16761.74 U16.4@15191.58,16763.35 ; R79.1@18461.5,16506.46 18462.48,16506.46 18476.18,16520.16 18476.18,16586.18 v2(18540,16650)
  SIG03 w6.5: v1(15140.56,16760.13) 15140.56,16933.79 15194.77,16988 18407,16988 18505,16890 18505,16685 v2(18540,16650)
NETR96_1: R96.1 U8.23 | length 131.7
  BOTTOM w6.5: U8.23@13257.65,14746.42 13273.58,14746.42 13309.7,14710.3 13359.79,14710.3 13364.79,14705.3 R96.1@13364.79,14697.8
NETR102_2: R102.2 U9.2 | length 109.1
  TOP w6.5: R102.2@13620,14698.5 13620,14662.24 13648.7,14633.54 13648.7,14603.11 U9.2@13650,14601.81
NETR106_2: R106.2 U9.4 | length 76.5
  TOP w6.5: R106.2@13623.48,14437.13 13624.41,14438.06 U9.4@13624.41,14513.23
NetR109_1: R109.1 U9.1 | length 102.7
  TOP w6.5: U9.1@13675.59,14601.81 13675.59,14640.04 13690,14654.45 R109.1@13690,14698.5
NETR142_2: R142.2 R172.1 U1.8 | length 3803.8
  TOP w6.5: U1.8@15698.27,15598.78 15698.27,15663.27 15716.95,15681.95 15716.95,15695.46 R172.1@15730,15708.5 15730,15709.49 15925,15904.49 v2(15925,16115)
  SIG03 w6.5: v2(15925,16115) 15922.7,16117.3 15922.7,16129.67 15918.21,16134.17 15918.21,16643.21 15990,16715 16645,16715 16720,16790 16763.89,16790 v2(16764.44,16790.56)
  BOTTOM w6.5: v2(16764.44,16790.56) 16800.87,16826.98 16800.87,16910.87 16830,16940 16833.51,16940 16836.99,16943.48 17674.71,16943.48 17698.19,16920 18230,16920 18315,16835 R142.2@18315,16787.61
NETR143_2: R143.2 R172.2 TP82.1 U2.8 | length 4281.3
  TOP w6.5: v2(15707,15880) 15707,15876.75 15720,15863.75 15720,15781.5 R172.2@15730,15771.5 ; U2.8@17403.27,15598.78 17403.71,15599.22 17403.71,15640.88 v2(17404.15,15641.32)
  SIG03 w6.5: v2(15707,15880) 15707,15644.72 15736.72,15615 16420.4,15615 16470.4,15665 17399.15,15665 17405,15659.14 17405,15642.17 v2(17404.15,15641.32) ; v2(18350,16000) 18350,16836.75 18355,16841.75 v2@18355,16845
  SIG04 w6.5: v2(17404.15,15641.32) 17538.83,15776 18301,15776 18350,15825 v2(18350,16000)
  BOTTOM w6.5: v2(15707,15880) 15708.36,15881.36 15708.36,15913.36 TP82.1@15709.72,15914.72 ; v2(18353,16847) 18353,16843.75 18361.64,16835.11 18361.64,16816.32 R143.2@18375.34,16802.62
NETR155_2: R155.2 U11.2 | length 329.7
  TOP w6.5: U11.2@16244.41,16215 16244.41,16080.59 16290.8,16034.2 16290.8,15941.63 16265.25,15916.08 R155.2@16264.27,15916.08
NETR160_2: R160.2 U12.2 | length 335.2
  TOP w6.5: U12.2@16396.18,16215 16396.18,16073.82 16445,16025 16445,15951.41 16409.36,15915.78 R160.2@16408.38,15915.78
NETR163_2: R163.2 U13.2 | length 328.5
  TOP w6.5: U13.2@16546.18,16215 16546.18,16068.82 16591.63,16023.37 16591.63,15941.64 16581.07,15931.08 16581.07,15930.09 16567.37,15916.39 R163.2@16566.38,15916.39
NETR169_2: R169.2 U14.2 | length 333.4
  TOP w6.5: U14.2@16697.8,16214.17 16697.8,16064.97 16745,16017.77 16745,15950.42 16710.29,15915.71 R169.2@16709.31,15915.71
NTC1: C206.2 R127.1 R152.1 RT3.2 | length 6827.7
  TOP w6.5: v2(18055.03,15945.02) R152.1@18055,15985.32
  SIG03 w6.5: v2(12756.5,15306) 12802.5,15260 v2@14205,15260
  SIG04 w6.5: v2(14210,15260) 14255,15260 14290,15295 14290,15985.81 14395.19,16091 15636,16091 15745,16200 15745,16537.37 15797.63,16590 16672.37,16590 16862.37,16400 17007.37,16400 17393.37,16014 17986.05,16014 v2(18055.03,15945.02)
  BOTTOM w6.5: RT3.2@12756.5,15278 v2(12756.5,15306) ; C206.2@18055,15918.62 v2(18055.03,15945.02)
NTC2: C207.2 R124.1 R153.1 RT4.2 | length 6038.9
  TOP w6.5: v2(18115.03,15945.02) R153.1@18115,15985.32
  SIG04 w6.5: v2(13625,15305) 13645,15285 14244.14,15285 14270,15310.86 14270,15995 14385,16110 15625,16110 15725,16210 15725,16540 15795,16610 16675,16610 16869,16416 17014,16416 17400,16030 18030.05,16030 v2(18115.03,15945.02)
  BOTTOM w6.5: RT4.2@13625,15278 v2(13625,15305) ; C207.2@18115,15918.62 v2(18115.03,15945.02) ; v2(18115.03,15945.02) R124.1@18115,15973.5
PA0_I2C0-SDA: R128.1 U10.33 | length 4421.9
  TOP w6.5: R128.1@17830,12545.04 v2(17830,12581.21)
  SIG04 w6.5: v2(17830,12581.21) 17831.49,12582.7 17831.49,12596.49 18486,13251 18486,15951.63 18251.63,16186 17958.11,16186 v2(17956.83,16187.28)
  BOTTOM w6.5: U10.33@17852.37,16198.14 17875.99,16198.14 17876.9,16197.24 17876.9,16190.86 17882.76,16185 17924.56,16185 17929.56,16190 17931.26,16188.3 17955.82,16188.3 v2(17956.83,16187.28)
PA1_I2C0-SCL: R123.1 U10.34 | length 4444.4
  TOP w6.5: R123.1@17760,12545.04 v2(17760,12581.21)
  SIG04 w6.5: v2(17760,12581.21) 17793.58,12581.21 18470,13257.63 18470,15945 18251,16164 17949,16164 17933.56,16179.44 v2(17905,16208)
  BOTTOM w6.5: U10.34@17852.37,16217.83 17853.28,16216.92 17894.83,16216.92 17903.75,16208 v2(17905,16208)
PA2_ROSC: R121.1 U10.42 | length 91.5
  BOTTOM w6.5: R121.1@17765,16385.18 17765.49,16385.18 17775.36,16375.31 U10.42@17852.37,16375.31
PA3_LFXIN: C196.2 U10.43 Y2.2 | length 261.6
  BOTTOM w6.5: C196.2@17620,16403.62 17646.81,16403.62 17649.96,16400.47 17685.47,16400.47 17700.16,16385.79 17705.75,16385.79 17720.43,16400.47 17720.43,16404.14 17730.5,16414.21 17790.79,16414.21 17810.01,16394.99 U10.43@17852.37,16394.99
PA4_LFXOUT: C202.2 U10.44 Y2.1 | length 270.6
  BOTTOM w6.5: C202.2@17620,16461.38 17661.58,16461.38 17684.41,16484.21 Y2.1@17690,16484.21 17704.69,16469.53 17755.22,16469.53 17809.16,16415.58 17851.47,16415.58 U10.44@17852.37,16414.68
PA5_HFXIN: C198.2 U10.45 Y3.3 | length 349.3
  BOTTOM w6.5: C198.2@17620,16613.62 17620,16614.69 17626.81,16621.5 Y3.3@17681.69,16621.5 17686.61,16621.5 17725,16583.11 17725,16522.37 17812.1,16435.27 17851.47,16435.27 U10.45@17852.37,16434.36
PA6_HFXOUT: C197.2 U10.46 Y3.1 | length 225
  BOTTOM w6.5: Y3.1@17768.31,16558.5 Y3.1@17771.19,16558.5 ; C197.2@17830,16566.38 17830,16565.31 17823.19,16558.5 Y3.1@17771.19,16558.5 ; U10.46@17852.37,16454.05 17851.47,16454.95 17815.05,16454.95 17771.19,16498.81 Y3.1@17771.19,16558.5
PA8_UART1-TX: J13.2 R166.2 U10.56 | length 6703.5
  SIG03 w6.5: J13.2@16515,12245 16538,12222 18339.37,12222 18540,12422.63 18540,15722.37 18284,15978.37 18284,16313.37 18212.37,16385 18132.37,16385 18063,16454.37 18063,16523.38 v2(18064.62,16525)
  BOTTOM w6.5: R166.2@18008.3,16738.04 18008.3,16687.92 18066.94,16629.28 U10.56@18066.94,16570.19 18066.38,16569.63 18066.38,16526.76 v2(18064.62,16525)
PA9_UART1-RX: J13.3 R167.2 U10.57 | length 6819.2
  SIG03 w6.5: J13.3@16423.69,12273.75 16491.44,12206 18346,12206 18556,12416 18556,15729 18300,15985 18300,16320 18215,16405 18135,16405 18085,16455 v2(18085,16490)
  BOTTOM w6.5: R167.2@18070.1,16738.35 18070.1,16665.1 18086.62,16648.58 U10.57@18086.62,16570.19 18086.62,16491.62 v2(18085,16490)
PA15_I2C1-SCL: J16.2 R134.1 U10.8 | length 280.1
  BOTTOM w6.5: U10.8@18301.19,16355.62 18302.09,16356.53 18390.9,16356.53 R134.1@18394.73,16360.36 18398.67,16360.36 18423.31,16385 18555,16385 J16.2@18565,16375
PA16_I2C1-SDA: J16.3 R136.1 U10.9 | length 289.1
  BOTTOM w6.5: U10.9@18301.19,16335.94 18368.18,16335.94 18391.14,16312.98 18399.01,16312.98 18421.82,16290.17 18534.95,16290.17 18550.13,16275 J16.3@18565,16275
PA18_BSL: J10.2 R126.2 U10.11 | length 444.6
  BOTTOM w6.5: U10.11@18301.19,16296.57 18358.53,16296.57 18390.87,16264.22 18398.74,16264.22 18426,16236.97 18486.13,16236.97 18495,16228.1 18495,16100 18553.74,16041.26 J10.2@18565,16041.26
PA19_SWDIO: J12.2 U10.12 | length 5614.2
  SIG03 w6.5: J12.2@17042.07,12273.75 17042.07,12288.18 17071.12,12317.23 17177.97,12317.23 17227.5,12267.7 17241.2,12254 18326.12,12254 18339.81,12267.7 18508,12435.88 18508,15709.12 18234.25,15982.87 18234.25,16265.95 v2(18251.59,16283.3)
  BOTTOM w6.5: v2(18251.59,16283.3) 18254.06,16280.82 18261.09,16280.82 18263.47,16278.44 18271.11,16278.44 18271.77,16277.79 18300.28,16277.79 U10.12@18301.19,16276.88
PA20_SWCLK: J12.1 U10.13 | length 5460.2
  SIG03 w6.5: J12.1@17142.07,12273.75 17169.55,12246.27 17177.82,12238 18332.75,12238 18524,12429.25 18524,15715.75 18255,15984.75 v2(18255,16255)
  BOTTOM w6.5: v2(18255,16255) 18256.1,16256.1 18300.09,16256.1 U10.13@18301.19,16257.2
PGOOD: R99.1 U8.28 | length 327.1
  SIG04 w6.5: v2(13172.85,14641.96) 13358.04,14641.96 v2(13396,14604)
  BOTTOM w6.5: v2(13172.85,14641.96) v2(13172.85,14641.96) 13172.93,14701.07 U8.28@13173,14701.14 ; R99.1@13396,14575 v2(13396,14604)
PVDD_1: C2.1 C3.2 C6.1 C7.1 C10.1 C11.1 C15.1 C16.1 C17.1 C18.1 C164.1 C216.1 C217.1 C218.1 C219.1 C220.1 J7.2 TP78.1 U1.22 U1.23 U1.24 U1.32 U1.33 U1.40 U1.41 U1.48 U1.49 U1.57 | length 282.3
  TOP w6.5: C2.1@15205.63,15302.73 15226.22,15282.14 15251.93,15282.14 15261.93,15272.14 C3.2@15295.63,15272.14 15309.33,15285.84 15309.33,15309.14 15315.19,15315 15375.75,15315 U1.24@15379.37,15311.38 U1.23@15379.37,15342.87 U1.22@15379.37,15374.37
  other v1: 14817.94,15916.18 14867.94,15916.18 14917.94,15916.18 14388.44,15920.86 14438.44,15920.86 14488.44,15920.86 14542.94,15921.18 14592.94,15921.18 14642.94,15921.18 14817.94,15966.18 14867.94,15966.18 14917.94,15966.18 14388.44,15970.86 14438.44,15970.86 14488.44,15970.86 14542.94,15971.18 14592.94,15971.18 14642.94,15971.18 14817.94,16016.18 14867.94,16016.18 14917.94,16016.18 14388.44,16020.86 14438.44,16020.86 14488.44,16020.86 14542.94,16021.18 14592.94,16021.18 14642.94,16021.18
  other v2: 15710,14770 15740,14770 15710,14795 15740,14795 15710,14820 15740,14820 16160.83,14850 16190.83,14850 16160.83,14885 16190.83,14885 15188.84,14891.26 15218.84,14891.26 15248.84,14891.26 15278.84,14891.26 15313.84,14891.26 15343.84,14891.26 15374.72,14891.36 16160,14915 16190,14915 15190,14930 15220,14930 15250,14930 15280,14930 15315,14930 15345,14930 15375.87,14930.11 16160,14945 16190,14945 15280,14970 15315,14970 15345,14970 15375.87,14970.11 15990,14975 15990,15005 15115,15265 15145,15265 15115,15295 15145,15295 15115,15325 15145,15325 15275,15325 15305,15325 16045,15340 16075,15340 16105,15340
PVDD_2: C54.1 C55.2 C58.1 C59.1 C62.1 C63.1 C67.1 C68.1 C69.1 C70.1 C165.1 C221.1 C222.1 C223.1 C224.1 C225.1 J8.2 TP81.1 U2.22 U2.23 U2.24 U2.32 U2.33 U2.40 U2.41 U2.48 U2.49 U2.57
  other v1: 15070,15920 15120,15920 15170,15920 15230,15920 15280,15920 15330,15920 15490,15920 15540,15920 15590,15920 15070,15970 15120,15970 15170,15970 15230,15970 15280,15970 15330,15970 15490,15970 15540,15970 15590,15970 15070,16020 15120,16020 15170,16020 15230,16020 15280,16020 15330,16020 15490,16020 15540,16020 15590,16020
  other v2: 17400,14780 17430,14780 17400,14805 17430,14805 17400,14830 17430,14830 16908.84,14901.26 16938.84,14901.26 16968.84,14901.26 16998.84,14901.26 17033.84,14901.26 17063.84,14901.26 17094.72,14901.36 17870,14920 17900,14920 16910,14940 16940,14940 16970,14940 17000,14940 17035,14940 17065,14940 17095.87,14940.11 17870,14945 17900,14945 17000,14980 17035,14980 17065,14980 17095.87,14980.11 17695,14980 17695,15015 16805,15260 16840,15260 16805,15290 16840,15290 16805,15320 16840,15320 16980,15320 16805,15345 16840,15345 16980,15345 17750.59,15348.31 17780.59,15348.31 17810.59,15348.31 16934.31,15348.62 16895,15350
PVDD_voltage_sense: R49.2 R51.1 R67.1 | length 7469.4
  SIG04 w6.5: v1(12045,16220) 12045,16438.15 12220.85,16614 13644,16614 13784,16754 14366,16754 14525,16595 15692.63,16595 15723.63,16626 17114,16626 17290,16450 17290,16266.91 17510.91,16046 18234,16046 18275,16005 v2(18275,15830)
  BOTTOM w6.5: v1(12045,16220) 12088.98,16220 12090,16218.98 ; R49.2@12090,16180 12090,16218.98 ; R51.1@12090,16248.5 12090,16218.98 ; R67.1@18240.55,15974.03 18240.55,15864.45 v2(18275,15830)
R\S\T\: C203.1 J12.3 R122.1 S1.4 U10.38 | length 6270.9
  TOP w6.5: S1.4@17737.44,16112.68 17737.44,16170.94 17775.01,16208.51 17796.67,16208.51 v2(17798.97,16210.81)
  SIG03 w6.5: J12.3@16942.07,12273.75 16953.98,12273.75 17013.46,12333.23 17184.59,12333.23 17247.82,12270 18319.49,12270 18492,12442.51 18492,15702.49 17964.49,16230 17818.16,16230 v2(17798.97,16210.81)
  BOTTOM w6.5: 17805,16220.09 17805,16278.71 17811.84,16285.56 17811.84,16286.2 17819.43,16293.79 17822.37,16293.79 17824.24,16295.66 17851.47,16295.66 U10.38@17852.37,16296.57
  BOTTOM w8: C203.1@17711.5,16075 17711.5,16137.09 17727.96,16153.55 17727.96,16157.49 17735.77,16165.3 R122.1@17739.7,16165.3 17743.64,16165.3 17782.04,16203.7 17788.61,16203.7
RT: R120.2 U8.22 | length 292.7
  BOTTOM w6.5: U8.22@13257.65,14766.1 13288.9,14766.1 13325,14730 13492.5,14730 13517.5,14705 R120.2@13525,14705
RXIN: C127.1 R42.2 U7.20 | length 4269.1
  TOP w6.5: U7.20@17101.14,16129.76 17142.01,16129.76 17152.35,16119.41 v2(17155.6,16119.41)
  SIG03 w6.5: v2(17650,15835) 17690,15835 17770,15755 17770,15555 18284.31,15040.69 v2(18284.31,12592.5)
  BOTTOM w6.5: v2(17155.6,16119.41) 17158.57,16116.44 17158.57,16106.16 17429.73,15835 v2(17650,15835) ; C127.1@18253.62,12595 18256.12,12592.5 v2(18284.31,12592.5) 18312.5,12592.5 R42.2@18315,12590
"SPILT TERM": C174.1 R69.1 R72.2 | length 196.5
  BOTTOM w6.5: C174.1@15156.5,16855 15222.68,16855 R72.2@15243.27,16834.41 ; R69.1@15242.91,16930 15243.27,16929.64 R72.2@15243.27,16834.41 ; R72.2@15243.27,16828.97 R72.2@15243.27,16834.41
